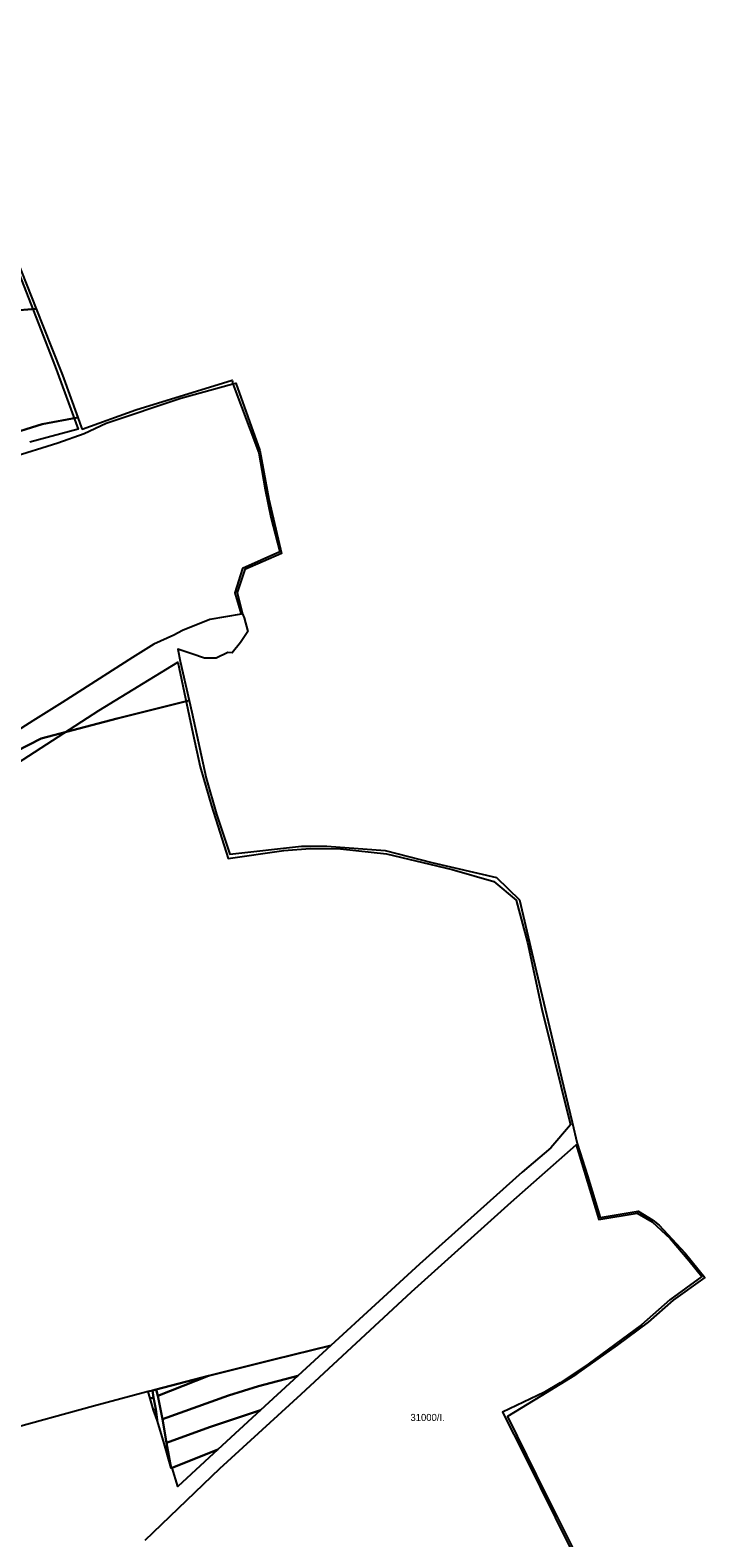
# Model space of a CAD drawing. Extents: x -532083 to -529270, y -1180561 to -1176456.
# Drawn here: x -530208 to -529731, y -1177521 to -1176456 of the extents above; entities that cross this region are included whole.
import ezdxf

# ---------------------------------------------------------------- set-up
doc = ezdxf.new("R2010")
doc.units = 0
doc.layers.add('95560013', color=7, linetype='Continuous')
doc.layers.add('95660013', color=7, linetype='Continuous')

msp = doc.modelspace()

# ---------------------------------------------------------------- linework, layer by layer
at = {"layer": '95560013'}
for points in [[(-530219.0883, -1176618.78145), (-530190.1893, -1176693.25345), (-530173.8473, -1176737.54745), (-530207.9223, -1176746.61545)], [(-530221.3573, -1176757.56345), (-530188.3163, -1176747.18245), (-530169.6073, -1176740.59345), (-530154.0823, -1176733.20645), (-530101.3363, -1176715.63745), (-530064.7593, -1176705.45345), (-530046.4373, -1176754.22445), (-530041.8253, -1176780.13045), (-530037.9033, -1176799.66045), (-530031.4803, -1176824.21345), (-530057.8673, -1176835.88045), (-530063.2493, -1176853.11945), (-530058.8583, -1176868.24045), (-530080.8323, -1176871.97345), (-530100.1863, -1176879.88845), (-530106.2903, -1176883.02445), (-530120.4683, -1176889.48845), (-530135.5223, -1176898.81545), (-530185.1103, -1176930.64345), (-530205.9203, -1176943.67145), (-530236.1413, -1176962.81445)], [(-530216.7773, -1176973.53945), (-530159.4063, -1176936.39445), (-530103.5993, -1176902.12745), (-530092.8643, -1176952.38145), (-530087.7113, -1176976.09345), (-530079.8313, -1177003.75845), (-530068.0123, -1177040.84745), (-530028.6123, -1177035.37545), (-530010.1243, -1177033.85545), (-529988.6063, -1177034.15945), (-529956.1763, -1177037.50345), (-529909.9163, -1177048.68045), (-529880.3993, -1177057.10045), (-529864.6933, -1177070.41045), (-529856.5693, -1177100.28945), (-529846.5503, -1177147.28145), (-529826.2783, -1177229.04845), (-529840.1833, -1177245.45745), (-529860.3593, -1177262.68745), (-529932.8373, -1177327.59345), (-529995.3763, -1177385.07345), (-530035.8083, -1177394.99345), (-530081.8123, -1177406.52245), (-530118.7423, -1177416.27045), (-530121.4683, -1177416.91545), (-530124.5543, -1177417.63045), (-530163.0193, -1177427.87145), (-530226.4153, -1177445.25745)], [(-530126.7073, -1177522.55345), (-530073.7763, -1177471.92045), (-530016.5393, -1177419.42845), (-529938.4963, -1177347.17945), (-529868.1993, -1177283.68845), (-529822.2913, -1177243.34745), (-529806.2573, -1177296.06545), (-529779.0883, -1177291.59745), (-529768.6213, -1177297.62845), (-529755.9283, -1177309.46745), (-529742.5663, -1177325.32745), (-529733.5983, -1177336.41945), (-529756.0573, -1177352.78945), (-529776.1203, -1177370.36145), (-529813.7513, -1177398.34545), (-529833.5143, -1177411.49545), (-529844.6683, -1177417.97245), (-529874.2153, -1177432.10445), (-529858.3653, -1177463.70545), (-529826.5603, -1177528.06745)]]:
    msp.add_lwpolyline(points, dxfattribs=at)
for points in [[(-530067.6523, -1177420.44845), (-530114.2993, -1177437.15945), (-530117.6313, -1177420.72645), (-530081.8123, -1177406.52245), (-530035.8083, -1177394.99345), (-529995.3763, -1177385.07345), (-530018.7833, -1177406.52245), (-530046.5493, -1177413.76445)], [(-530081.8123, -1177406.52245), (-530117.6313, -1177420.72645), (-530118.7423, -1177416.27045)], [(-530081.1453, -1177442.72945), (-530111.4113, -1177453.87045), (-530114.2993, -1177437.15945), (-530067.6523, -1177420.44845), (-530046.5493, -1177413.76445), (-530018.7833, -1177406.52245), (-530045.0493, -1177430.75345)], [(-530123.1093, -1177422.57145), (-530124.5543, -1177417.63045), (-530121.4683, -1177416.91545), (-530120.8023, -1177421.73045)], [(-530119.1243, -1177430.14645), (-530120.8023, -1177421.73045), (-530121.4683, -1177416.91545), (-530118.7423, -1177416.27045), (-530117.6313, -1177420.72645), (-530114.2993, -1177437.15945), (-530111.4113, -1177453.87045), (-530108.3193, -1177471.66345), (-530113.7373, -1177452.73545), (-530118.0333, -1177437.93145)], [(-530120.8023, -1177430.77845), (-530123.1093, -1177422.57145), (-530120.8023, -1177421.73045), (-530119.1243, -1177430.14645)], [(-530118.0333, -1177437.93145), (-530120.8023, -1177430.77845), (-530119.1243, -1177430.14645)], [(-530075.2513, -1177458.54545), (-530107.5713, -1177471.47545), (-530108.3193, -1177471.66345), (-530111.4113, -1177453.87045), (-530081.1453, -1177442.72945), (-530045.0493, -1177430.75345)], [(-530075.2513, -1177458.54545), (-530103.4613, -1177484.59345), (-530107.5713, -1177471.47545)]]:
    msp.add_lwpolyline(points, close=True, dxfattribs=at)
at = {"layer": '95660013'}
msp.add_lwpolyline([(-530339.8753, -1176652.00045), (-530366.8123, -1176626.00045), (-530384.3753, -1176603.00045), (-530395.5003, -1176573.00045), (-530401.6873, -1176519.00045), (-530401.4093, -1176506.37645), (-530397.7873, -1176504.78445), (-530363.8373, -1176489.74845), (-530298.8543, -1176460.89445), (-530283.3013, -1176455.55145), (-530258.2053, -1176516.84145), (-530234.7283, -1176574.37945), (-530203.5463, -1176652.48045), (-530221.3123, -1176654.00045), (-530261.1873, -1176663.00045), (-530289.6253, -1176668.00045), (-530309.3123, -1176667.00045), (-530324.8753, -1176663.00045)], close=True, dxfattribs=at)
for points in [[(-530221.3123, -1176654.00045), (-530203.5463, -1176652.48045), (-530192.6343, -1176679.81045), (-530184.8703, -1176699.44345), (-530174.1323, -1176729.16345), (-530199.3753, -1176734.00045), (-530253.6873, -1176751.00045)], [(-530253.6873, -1176751.00045), (-530199.3753, -1176734.00045), (-530174.1323, -1176729.16345), (-530171.4453, -1176736.60045), (-530171.1213, -1176737.57445), (-530133.2853, -1176723.87545), (-530065.0993, -1176702.89445), (-530064.7593, -1176705.45345), (-530062.5483, -1176704.94145), (-530045.7143, -1176752.70345), (-530039.3793, -1176786.88145), (-530030.2523, -1176825.31145), (-530056.2203, -1176836.66045), (-530061.6503, -1176852.86445), (-530057.9473, -1176867.92745), (-530056.7133, -1176870.81645), (-530054.0393, -1176880.51445), (-530059.1813, -1176888.35445), (-530065.1463, -1176895.57645), (-530068.2323, -1176895.37045), (-530076.4593, -1176899.29145), (-530084.6873, -1176899.29145), (-530093.7383, -1176896.40245), (-530103.6113, -1176893.10045), (-530101.9653, -1176901.35445), (-530095.5503, -1176929.22445), (-530146.3123, -1176942.00045), (-530200.1253, -1176956.00045), (-530227.1873, -1176970.00045)], [(-530227.1873, -1176970.00045), (-530200.1253, -1176956.00045), (-530146.3123, -1176942.00045), (-530095.5503, -1176929.22445), (-530093.6273, -1176937.57745), (-530083.6113, -1176984.13845), (-530076.2833, -1177009.62445), (-530066.8513, -1177037.74145), (-530016.2683, -1177032.10345), (-529998.3363, -1177032.10345), (-529957.1203, -1177035.32545), (-529924.2013, -1177043.64845), (-529878.4353, -1177054.38745), (-529862.1783, -1177070.14845), (-529853.6173, -1177107.44445), (-529832.6783, -1177195.95245), (-529825.1173, -1177227.23945), (-529821.5733, -1177242.29045), (-529814.1763, -1177265.18145), (-529805.3413, -1177294.63845), (-529778.5753, -1177290.20645), (-529768.1813, -1177296.46345), (-529763.7633, -1177300.11245), (-529745.1873, -1177319.86145), (-529731.4123, -1177337.02345), (-529753.8523, -1177353.07045), (-529771.4043, -1177368.67245), (-529793.3993, -1177384.71945), (-529820.5053, -1177404.11045), (-529823.4153, -1177406.33745), (-529847.2403, -1177420.82145), (-529870.7883, -1177435.22545), (-529850.3993, -1177476.42045), (-529810.6643, -1177556.14645)]]:
    msp.add_lwpolyline(points, dxfattribs=at)

# ---------------------------------------------------------------- texts
msp.add_text('31000/I.', height=5, rotation=359.99999997, dxfattribs=at).set_placement((-529939.2553, -1177438.40108))

doc.saveas('drawing.dxf')
